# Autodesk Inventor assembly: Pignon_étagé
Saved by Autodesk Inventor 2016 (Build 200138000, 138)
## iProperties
Created: 2013-08
Part Number: Pignon_étagé
Document SubType Name: Assembly
Designer: hilarion
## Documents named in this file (2)
- S:\TSTI2D\Documents en consultation\etude de cas 1  webcam\Webcam motorisee\Pignon_étagé.iam
- S:\TSTI2D\Documents en consultation\etude de cas 1  webcam\Webcam motorisee\Roue dentée Intermédiaire 2.ipt
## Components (1 placed, 1 different names)
1. Roue dentée Intermédiaire 2:1
